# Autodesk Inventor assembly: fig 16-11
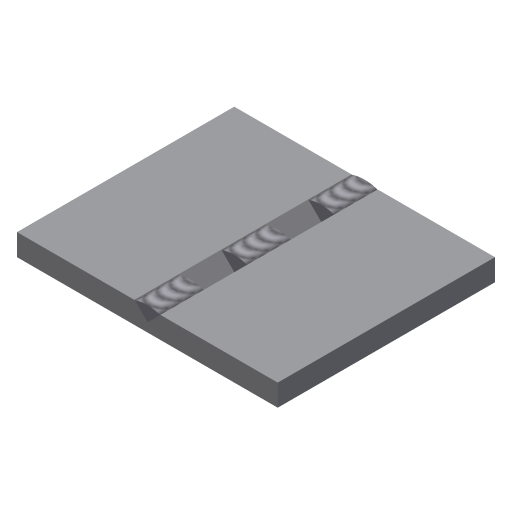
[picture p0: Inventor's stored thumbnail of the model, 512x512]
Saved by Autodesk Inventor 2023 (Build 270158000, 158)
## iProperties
Created: 2005-03
Part Number: fig 16-11
Document SubType Name: Weldment
Designer: CADCIM
Manufacturer: Standard
Standards Organization: Custom
Author: CADCIM
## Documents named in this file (2)
- D:\PROJECTS\Project 2022\Autodesk Inventor For Professional 2023\RESOURCES INVENTOR 2023\RESOURCES INVENTOR 2023\Inventor_2023_Part\Inventor_2023_Part\c16_Inv_2023_prt\fig 16-11\fig 16-11.iam
- D:\PROJECTS\Project 2022\Autodesk Inventor For Professional 2023\RESOURCES INVENTOR 2023\RESOURCES INVENTOR 2023\Inventor_2023_Part\Inventor_2023_Part\c16_Inv_2023_prt\fig 16-11\Part1.ipt
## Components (2 placed, 1 different names)
1. Part1:1 — Mate:1, Flush:1, Flush:2
2. Part1:2 — Mate:1, Flush:1, Flush:2
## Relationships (3: Flush 2, Mate 1)
- Mate:1: Part1:1 ↔ Part1:2
- Flush:1: Part1:1 ↔ Part1:2
- Flush:2: Part1:1 ↔ Part1:2
